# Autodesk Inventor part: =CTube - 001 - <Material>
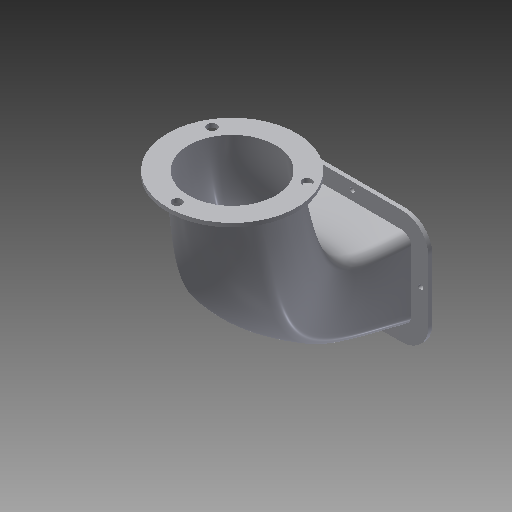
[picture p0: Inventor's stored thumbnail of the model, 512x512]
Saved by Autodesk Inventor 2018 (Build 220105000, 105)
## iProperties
Created: 2006-10
Part Number: =CTube - 001 - <Material>
Document SubType Name: Modeling
Designer: Autodesk, Inc.
Density: 2.71 g/cm^3
Material: Aluminum-6061
Description: Exhaust Tube - Transitional
Mass: 16972.7 g
Surface Area: 12672.8 cm^2
Volume: 6263 cm^3
Appearance: Aluminum - Flat
Author: Autodesk, Inc.
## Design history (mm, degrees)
node "Distance Plane"
sketch "Sketch2"
  geometry: L1 (-78.628, 403.823)-(-78.628, 548.123); L2 (-78.628, 403.823)-(46.339, 331.673); L3 (-78.628, 403.823)-(-203.596, 331.673); C1 r 114.3 at (-78.628, 403.823); C2 r 169.3 at (-78.628, 403.823); C3 r 12.7 at (-78.628, 548.123); C4 r 12.7 at (46.339, 331.673); C5 r 12.7 at (-203.596, 331.673); A1 r 144.3 centre (-78.628, 403.823) between (-78.628, 548.123) and (46.339, 331.673); 1 further point
  constraints: 6 centre point, 6 end point, 3 point on circle, 2 coincident, 2 equal radius, 1 vertical
  dimensions: "d22" = 228.6 diameter of C1; "d23" = 338.6 diameter of C2 (computed from d22); "d24" = 288.6 diameter of A1 (computed from d22); "d88" = 120 deg angle of L3 L1; "d89" = 120 deg angle of L2 L1 (= d88); "d113" = 25.4 diameter of C3
node "Angle Plane"
  workaxis "Work Axis1"
feature "Stitch Surface4" dims "d138" = 0.254 (derived)
thicken "Thicken4" dims "d137" = 10.16
body "Solid1"
sketch "3D Sketch3" dims "d14" = 25.4, "d15" = 25.4
body "Srf2"
body "Srf3"
body "Srf1"
body "Srf4"
patch "Boundary Patch1"
patch "Boundary Patch2"
feature "LoftSrf4" dims "d115" = 0, "d116" = 90 deg, "d117" = 0, "d118" = 90 deg, "d119" = 0, "d120" = 90 deg, "d121" = 0, "d122" = 0, "d123" = 4042.21261, "d124" = 10.00133, "d125" = 660.87569, "d126" = 10, "d127" = 5491.09151, "d128" = 10.00086, "d129" = 453.91524, "d130" = 6.86839, "d131" = 3999.992, "d132" = 7.93428, "d133" = 257.666, "d134" = 3.89886, "d135" = 3999.992, "d136" = 8.66046
other parameters: "d2" = 406.4, "d26" = 10 deg, "d114" = 12.7
